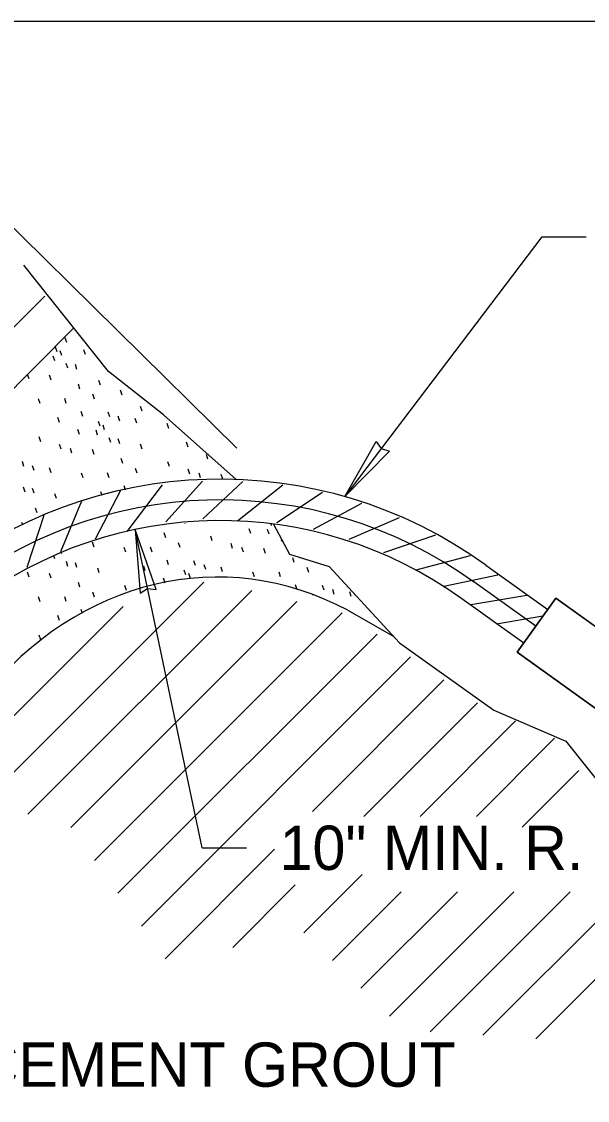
# Model space of a CAD drawing. Extents: x 99861 to 103151, y 100000 to 102076.
# Drawn here: x 101972.9 to 102177.4, y 101686.1 to 102076 of the extents above; entities that cross this region are included whole.
import ezdxf

# ---------------------------------------------------------------- set-up
doc = ezdxf.new("R2010")
doc.units = 0
for name, color, linetype in [('Level 1', 7, 'Continuous'), ('Level 10', 7, 'Continuous'), ('Level 15', 7, 'Continuous'), ('Level 2', 7, 'Continuous'), ('Level 20', 7, 'Continuous'), ('Level 4', 7, 'Continuous'), ('Level 6', 7, 'Continuous'), ('Level 8', 7, 'Continuous')]:
    doc.layers.add(name, color=color, linetype=linetype)

msp = doc.modelspace()

# ---------------------------------------------------------------- linework, layer by layer
at = {"layer": 'Level 1'}
for p, q in [((102140.69, 101879.55), (102140.69, 101879.54)), ((102132, 101867.34), (102132.01, 101867.33))]:
    msp.add_line(p, q, dxfattribs=at)
msp.add_lwpolyline([(99861, 100000), (103150, 100000), (103150, 102076), (99861, 102076)], close=True, dxfattribs=at)
for points in [[(102140.69, 101879.54), (102163.16, 101863.54)], [(102154.41, 101851.38), (102132, 101867.34)]]:
    msp.add_lwpolyline(points, dxfattribs=at)
for radius, start, end in [(164.08, 54.1697, 129.2321), (149.1, 54.1279, 127.2134)]:
    msp.add_arc((102044.64, 101746.52), radius, start, end, dxfattribs=at)
at = {"layer": 'Level 10'}
for p, q in [((101896.1, 101891.64), (101981.24, 101976.77)), ((101896.1, 101891.64), (101981.24, 101976.77)), ((101958.77, 101793.43), (102038.74, 101873.4)), ((101975.17, 101789.47), (102056.08, 101870.38)), ((101942.36, 101797.39), (102009.57, 101864.6)), ((101990.73, 101784.66), (102072.43, 101866.37)), ((101999.23, 101772.8), (102088.79, 101862.35)), ((101999.23, 101772.8), (102088.79, 101862.35)), ((102007.73, 101760.94), (102101.43, 101854.63)), ((102016.24, 101749.07), (102113.5, 101846.34)), ((102078.04, 101790.51), (102125.58, 101838.05)), ((102096.62, 101788.73), (102137.66, 101829.76)), ((102116.99, 101788.73), (102151.5, 101823.24)), ((102137.35, 101788.73), (102165.56, 101816.94)), ((102137.35, 101788.73), (102165.56, 101816.94)), ((102153.87, 101784.88), (102174.31, 101805.32)), ((102024.74, 101737.21), (102064.35, 101776.82)), ((102158.82, 101708.38), (102221.14, 101770.7)), ((102074.94, 101746.68), (102096, 101767.74)), ((102049.21, 101741.32), (102071.84, 101763.95)), ((102085.25, 101736.63), (102110.06, 101761.43)), ((102085.25, 101736.63), (102110.06, 101761.43)), ((102095.57, 101726.58), (102130.42, 101761.43)), ((102105.88, 101716.53), (102150.79, 101761.43)), ((102120.55, 101710.83), (102171.15, 101761.43)), ((102120.55, 101710.83), (102171.15, 101761.43)), ((102139.68, 101709.6), (102191.52, 101761.43))]:
    msp.add_line(p, q, dxfattribs=at)
at = {"layer": 'Level 15'}
for p, q in [((102050.67, 101921.83), (101941.75, 102029.12)), ((102160.94, 101998.19), (102089.69, 101904.29)), ((102160.94, 101998.19), (102176.94, 101998.19)), ((102038.14, 101777.37), (102013.92, 101892.41)), ((102038.14, 101777.37), (102054.14, 101777.37))]:
    msp.add_line(p, q, dxfattribs=at)
for points in [[(102089.69, 101904.29), (102101.11, 101924.28), (102102.85, 101921.64), (102105.87, 101920.67)], [(102013.92, 101892.41), (102015.7, 101869.46), (102018.4, 101871.11), (102021.54, 101870.69)]]:
    msp.add_lwpolyline(points, close=True, dxfattribs=at)
at = {"layer": 'Level 2'}
for p, q in [((101991.76, 101965.28), (101815.03, 101787.34)), ((102090.8, 101863.22), (102107.44, 101853.78))]:
    msp.add_line(p, q, dxfattribs=at)
for points in [[(102050.48, 101910.49), (102024.14, 101933.83), (102004.3, 101949.53), (101973.72, 101987.92)], [(102063.91, 101894.36), (102069.69, 101883.44), (102084.09, 101879.05), (102109.55, 101851.4)], [(102109.55, 101851.4), (102143.61, 101827.11), (102169.61, 101815.92), (102185.33, 101796.3), (102238.99, 101755.45), (102275, 101728.75), (102305.41, 101711.87), (102328.83, 101696.29), (102371.7, 101667.89), (102390.96, 101654.77), (102398.39, 101648.87), (102449.8, 101608.01), (102535.32, 101553.7), (102542.03, 101551.35)]]:
    msp.add_lwpolyline(points, dxfattribs=at)
msp.add_ellipse((102043.57, 101727.18), major_axis=(0, 148.04), ratio=0.808892, start_param=5.877818, end_param=7.068912, dxfattribs=at)
at = {"layer": 'Level 4'}
for p, q in [((102023.72, 101908.62), (102010.88, 101891.74)), ((102038.25, 101909.84), (102024.97, 101895.16)), ((102052.83, 101909.77), (102038.36, 101896.26)), ((102067.34, 101908.41), (102050.91, 101895.48)), ((102008.63, 101906.52), (101999.47, 101888.97)), ((102081.68, 101905.76), (102065.14, 101894.87)), ((101994.54, 101902.62), (101986.89, 101884.35)), ((102095.73, 101901.84), (102078.33, 101892.39)), ((101980.86, 101897.48), (101974.78, 101878.64)), ((102109.38, 101896.69), (102091.24, 101888.75)), ((102122.52, 101890.35), (102103.78, 101883.97)), ((102135.04, 101882.87), (102115.4, 101877.75)), ((102145.09, 101875.92), (102125.5, 101871.78)), ((102155.54, 101868.54), (102135.31, 101865.14)), ((102161.38, 101861.07), (102144.53, 101858.24))]:
    msp.add_line(p, q, dxfattribs=at)
msp.add_lwpolyline([(102158.79, 101857.47), (102136.35, 101873.45)], dxfattribs=at)
msp.add_arc((102044.64, 101746.52), 156.58, 54.1697, 129.2321, dxfattribs=at)
at = {"layer": 'Level 6'}
for p, q in [((102152.06, 101848.1), (102166.07, 101867.59)), ((102166.07, 101867.59), (102212.55, 101834.17)), ((102198.54, 101814.68), (102152.06, 101848.1))]:
    msp.add_line(p, q, dxfattribs=at)
msp.add_lwpolyline([(102198.54, 101814.68), (102212.55, 101834.17), (102166.07, 101867.59), (102152.06, 101848.1), (102198.54, 101814.68)], dxfattribs=at)
at = {"layer": 'Level 8'}
for p, q in [((101989.22, 101959.96), (101988.65, 101961.71)), ((101985.73, 101956.59), (101985.16, 101958.34)), ((101984.88, 101953.37), (101984.31, 101955.12)), ((101987.4, 101955.29), (101986.83, 101957.03)), ((101995.95, 101955.66), (101995.38, 101957.41)), ((101989.62, 101950.69), (101989.05, 101952.44)), ((101992.89, 101950.26), (101992.32, 101952.01)), ((101975.59, 101946.85), (101975.06, 101948.46)), ((101983.57, 101946.42), (101983, 101948.17)), ((102001.42, 101944.58), (102000.85, 101946.33)), ((101993.97, 101943.15), (101993.4, 101944.89)), ((102009.19, 101940.98), (102008.62, 101942.73)), ((101979.58, 101937.93), (101979, 101939.67)), ((101989.03, 101937.97), (101988.46, 101939.72)), ((101999.18, 101939.58), (101998.61, 101941.32)), ((101995.01, 101933.3), (101994.44, 101935.05)), ((102004.73, 101933.11), (102004.16, 101934.85)), ((102016.45, 101935.17), (102015.88, 101936.92)), ((101986.59, 101931.14), (101986.02, 101932.89)), ((102001.23, 101929.73), (102000.66, 101931.48)), ((102008.42, 101931.61), (102007.85, 101933.36)), ((102014.56, 101930.83), (102013.99, 101932.57)), ((102026.08, 101928.97), (102025.51, 101930.71)), ((101993.76, 101926.77), (101993.18, 101928.52)), ((102000.38, 101926.51), (101999.81, 101928.26)), ((102002.91, 101928.43), (102002.34, 101930.18)), ((101979.8, 101924.13), (101979.23, 101925.88)), ((101987.17, 101921.42), (101986.6, 101923.17)), ((102005.12, 101923.83), (102004.55, 101925.58)), ((102008.4, 101923.4), (102007.83, 101925.15)), ((102016.47, 101921.49), (102015.9, 101923.23)), ((102033.09, 101922.18), (102032.52, 101923.93)), ((101991.09, 101919.99), (101990.52, 101921.74)), ((101999.07, 101919.57), (101998.5, 101921.31)), ((102040.26, 101917.81), (102039.68, 101919.56)), ((101973.73, 101915.21), (101973.16, 101916.96)), ((101977.43, 101913.72), (101976.86, 101915.46)), ((102009.48, 101916.29), (102008.91, 101918.04)), ((102026.3, 101915.17), (102025.73, 101916.92)), ((101983.56, 101912.93), (101982.99, 101914.68)), ((101995.08, 101911.07), (101994.51, 101912.82)), ((102004.54, 101911.11), (102003.96, 101912.86)), ((102014.69, 101912.72), (102014.12, 101914.47)), ((102033.67, 101912.46), (102033.1, 101914.21)), ((102037.59, 101911.03), (102037.02, 101912.77)), ((102045.58, 101910.61), (102045, 101912.35)), ((101974.13, 101905.94), (101973.56, 101907.68)), ((101977.4, 101905.51), (101976.83, 101907.25)), ((102010.46, 101906.64), (102009.95, 101908.19)), ((101985.47, 101903.59), (101984.9, 101905.34)), ((102001.95, 101904.72), (102001.52, 101906.03)), ((101978.48, 101898.39), (101977.91, 101900.14)), ((101973.29, 101893.99), (101972.97, 101894.97)), ((102031.97, 101894.63), (102031.94, 101894.72)), ((102055.76, 101890.95), (102055.19, 101892.7)), ((102062.39, 101890.7), (102061.82, 101892.44)), ((102063.24, 101893.92), (102063.08, 101894.41)), ((101999.07, 101886.08), (101998.5, 101887.82)), ((102024.98, 101889.43), (102024.41, 101891.18)), ((102030.19, 101885.86), (102029.62, 101887.61)), ((102041.81, 101888.31), (102041.24, 101890.06)), ((102067.13, 101888.02), (102066.9, 101888.7)), ((101987.42, 101883.68), (101987.35, 101883.91)), ((102010.59, 101884.22), (102010.02, 101885.96)), ((102020.04, 101884.26), (102019.47, 101886)), ((102049.18, 101885.6), (102048.61, 101887.35)), ((102053.1, 101884.17), (102052.53, 101885.92)), ((102061.08, 101883.75), (102060.51, 101885.5)), ((101984.89, 101881.76), (101984.53, 101882.86)), ((101989.63, 101879.08), (101989.06, 101880.83)), ((101992.91, 101878.65), (101992.34, 101880.4)), ((102026.03, 101879.59), (102025.45, 101881.33)), ((102035.74, 101879.39), (102035.17, 101881.14)), ((102039.43, 101877.9), (102038.86, 101879.65)), ((102071.48, 101880.47), (102070.91, 101882.22)), ((101975.6, 101875.24), (101975.03, 101876.98)), ((101983.59, 101874.82), (101983.01, 101876.56)), ((102000.98, 101876.73), (102000.41, 101878.48)), ((102017.6, 101877.43), (102017.03, 101879.18)), ((102032.24, 101876.02), (102031.67, 101877.77)), ((102033.92, 101874.72), (102033.35, 101876.46)), ((102045.57, 101877.11), (102045, 101878.86)), ((102057.09, 101875.25), (102056.52, 101877)), ((102066.54, 101875.3), (102065.97, 101877.04)), ((102076.69, 101876.9), (102076.12, 101878.65)), ((101993.99, 101871.54), (101993.42, 101873.28)), ((102010.81, 101870.42), (102010.24, 101872.17)), ((102024.77, 101873.06), (102024.2, 101874.8)), ((102030.92, 101874.24), (102030.82, 101874.55)), ((102072.53, 101870.63), (102071.95, 101872.37)), ((102082.24, 101870.43), (102081.67, 101872.18)), ((101979.59, 101866.32), (101979.02, 101868.07)), ((101989.05, 101866.36), (101988.47, 101868.11)), ((101999.2, 101867.97), (101998.63, 101869.71)), ((102078.24, 101868.6), (102078.17, 101868.81)), ((102085.93, 101868.94), (102085.36, 101870.68)), ((102092.07, 101868.15), (102091.5, 101869.9)), ((101986.6, 101859.54), (101986.03, 101861.28)), ((101994.91, 101862.07), (101994.46, 101863.44)), ((101979.82, 101852.52), (101979.25, 101854.27))]:
    msp.add_line(p, q, dxfattribs=at)

# ---------------------------------------------------------------- texts
at = {"layer": 'Level 20'}
for s, p in [('10" MIN. R.', (102066.14, 101769.37)), ('CEMENT GROUT', (101956.28, 101691))]:
    msp.add_text(s, height=16, dxfattribs=at).set_placement(p)

doc.saveas('drawing.dxf')
